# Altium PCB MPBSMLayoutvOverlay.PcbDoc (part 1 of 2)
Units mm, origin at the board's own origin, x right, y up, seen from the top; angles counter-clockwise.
Board outline 99.82 x 98.31 mm, 4 copper layers (Top Layer, Power, GroundPlane, Bottom Layer), stack 2.286 mm thick; 142 components, 77 nets, 390 pads, 126 vias.
Unrouted connection lines stored in the file: 1.
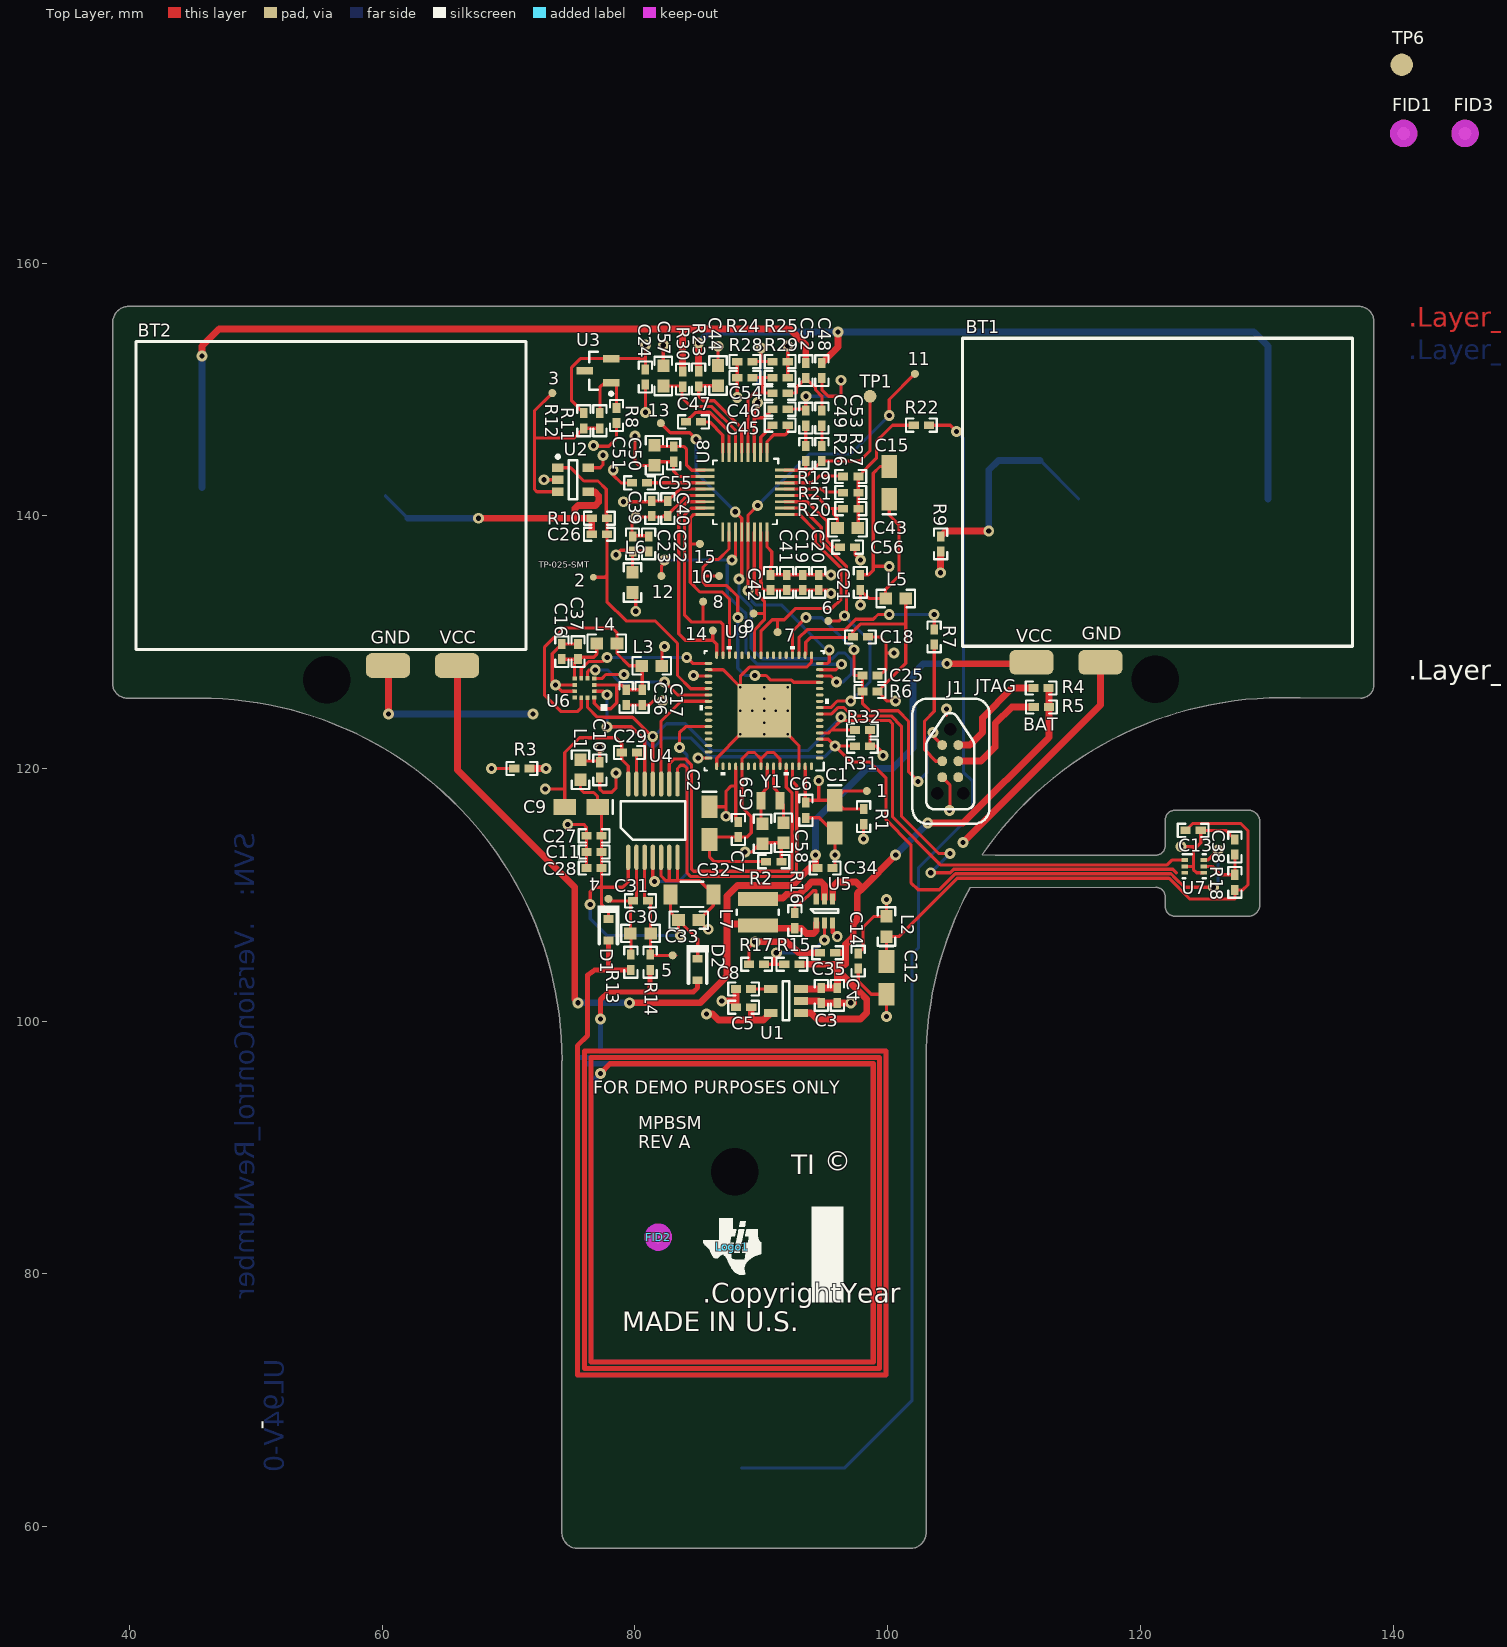
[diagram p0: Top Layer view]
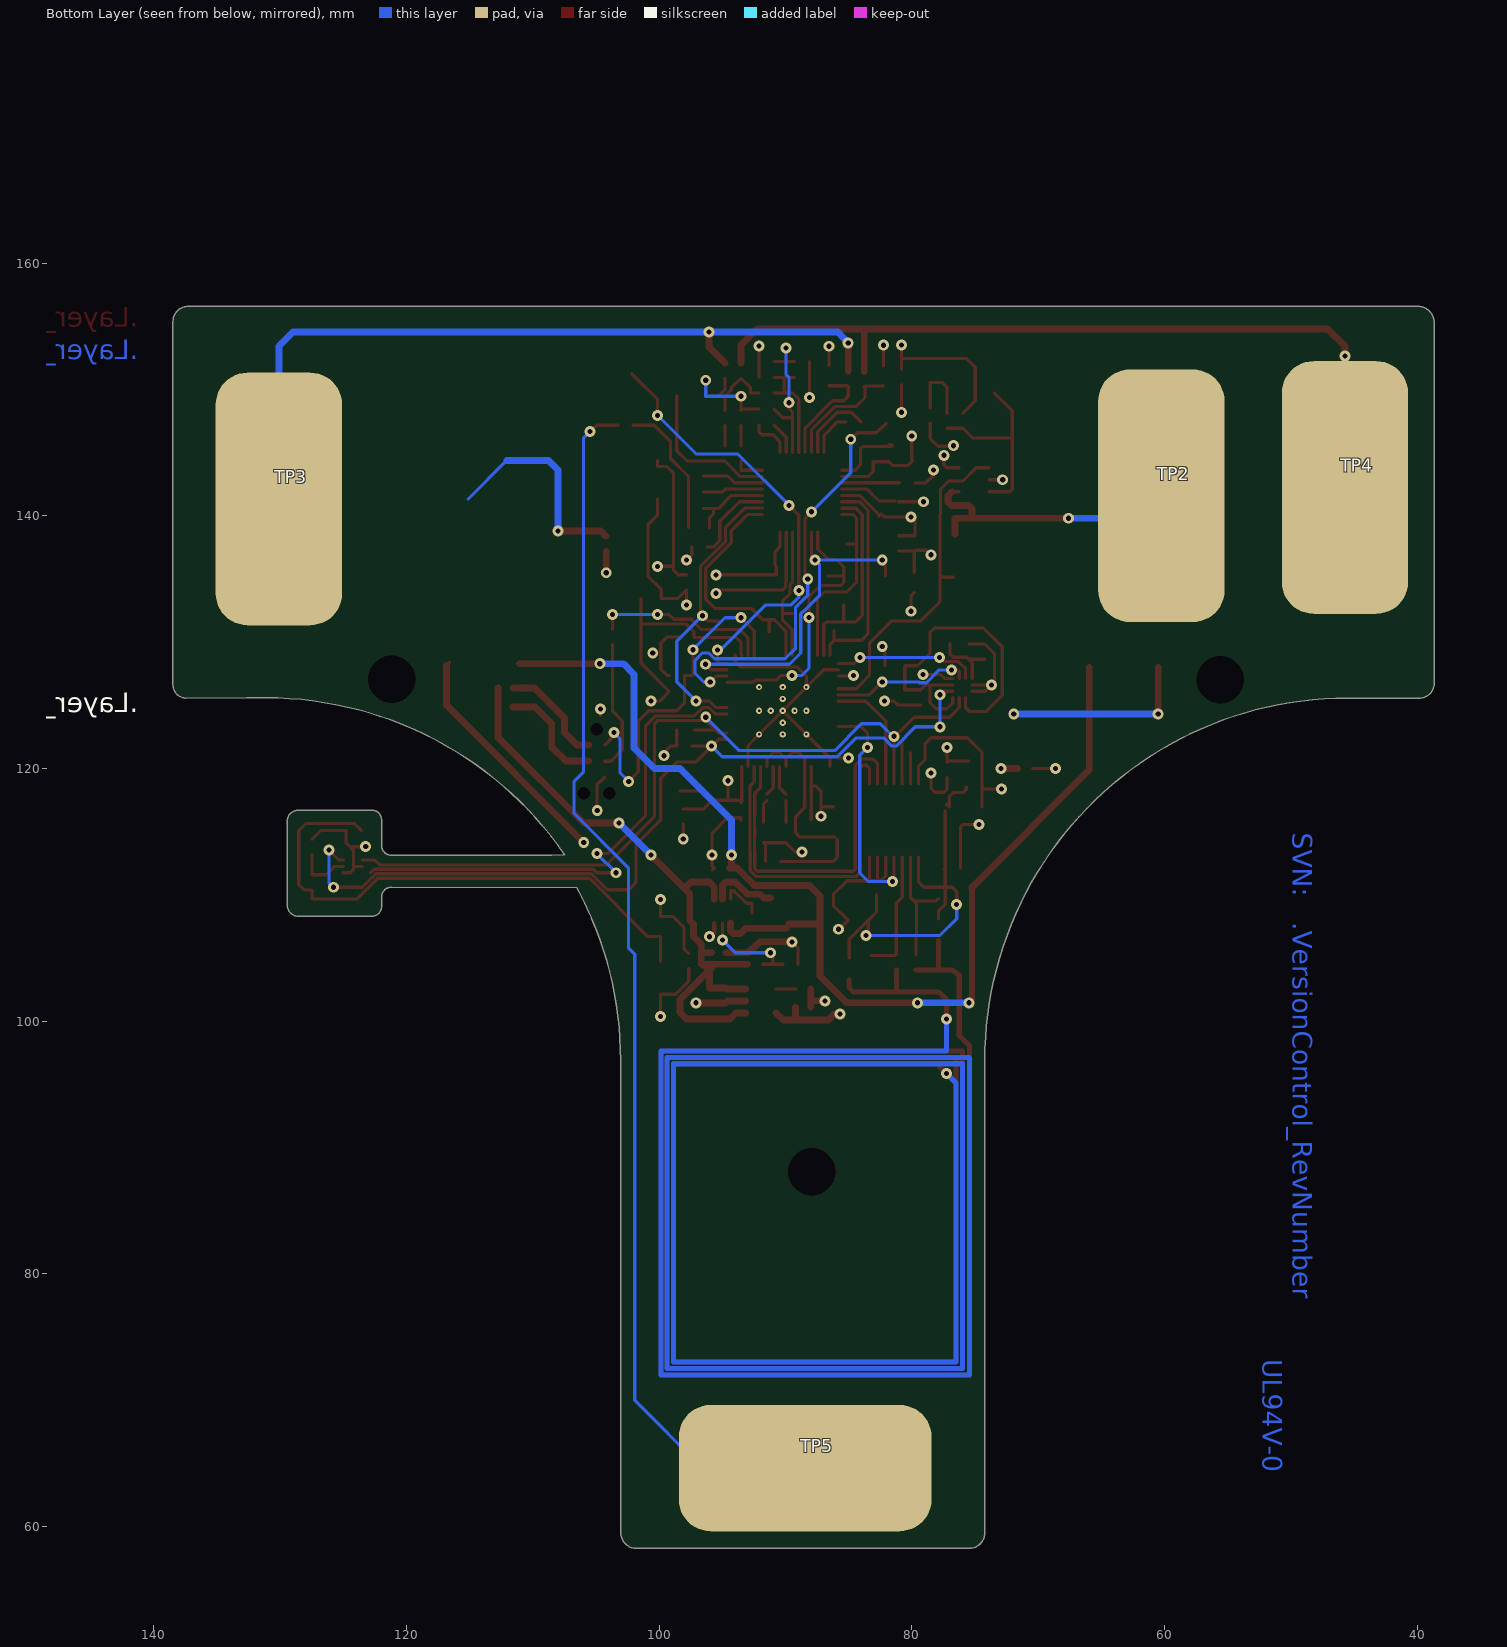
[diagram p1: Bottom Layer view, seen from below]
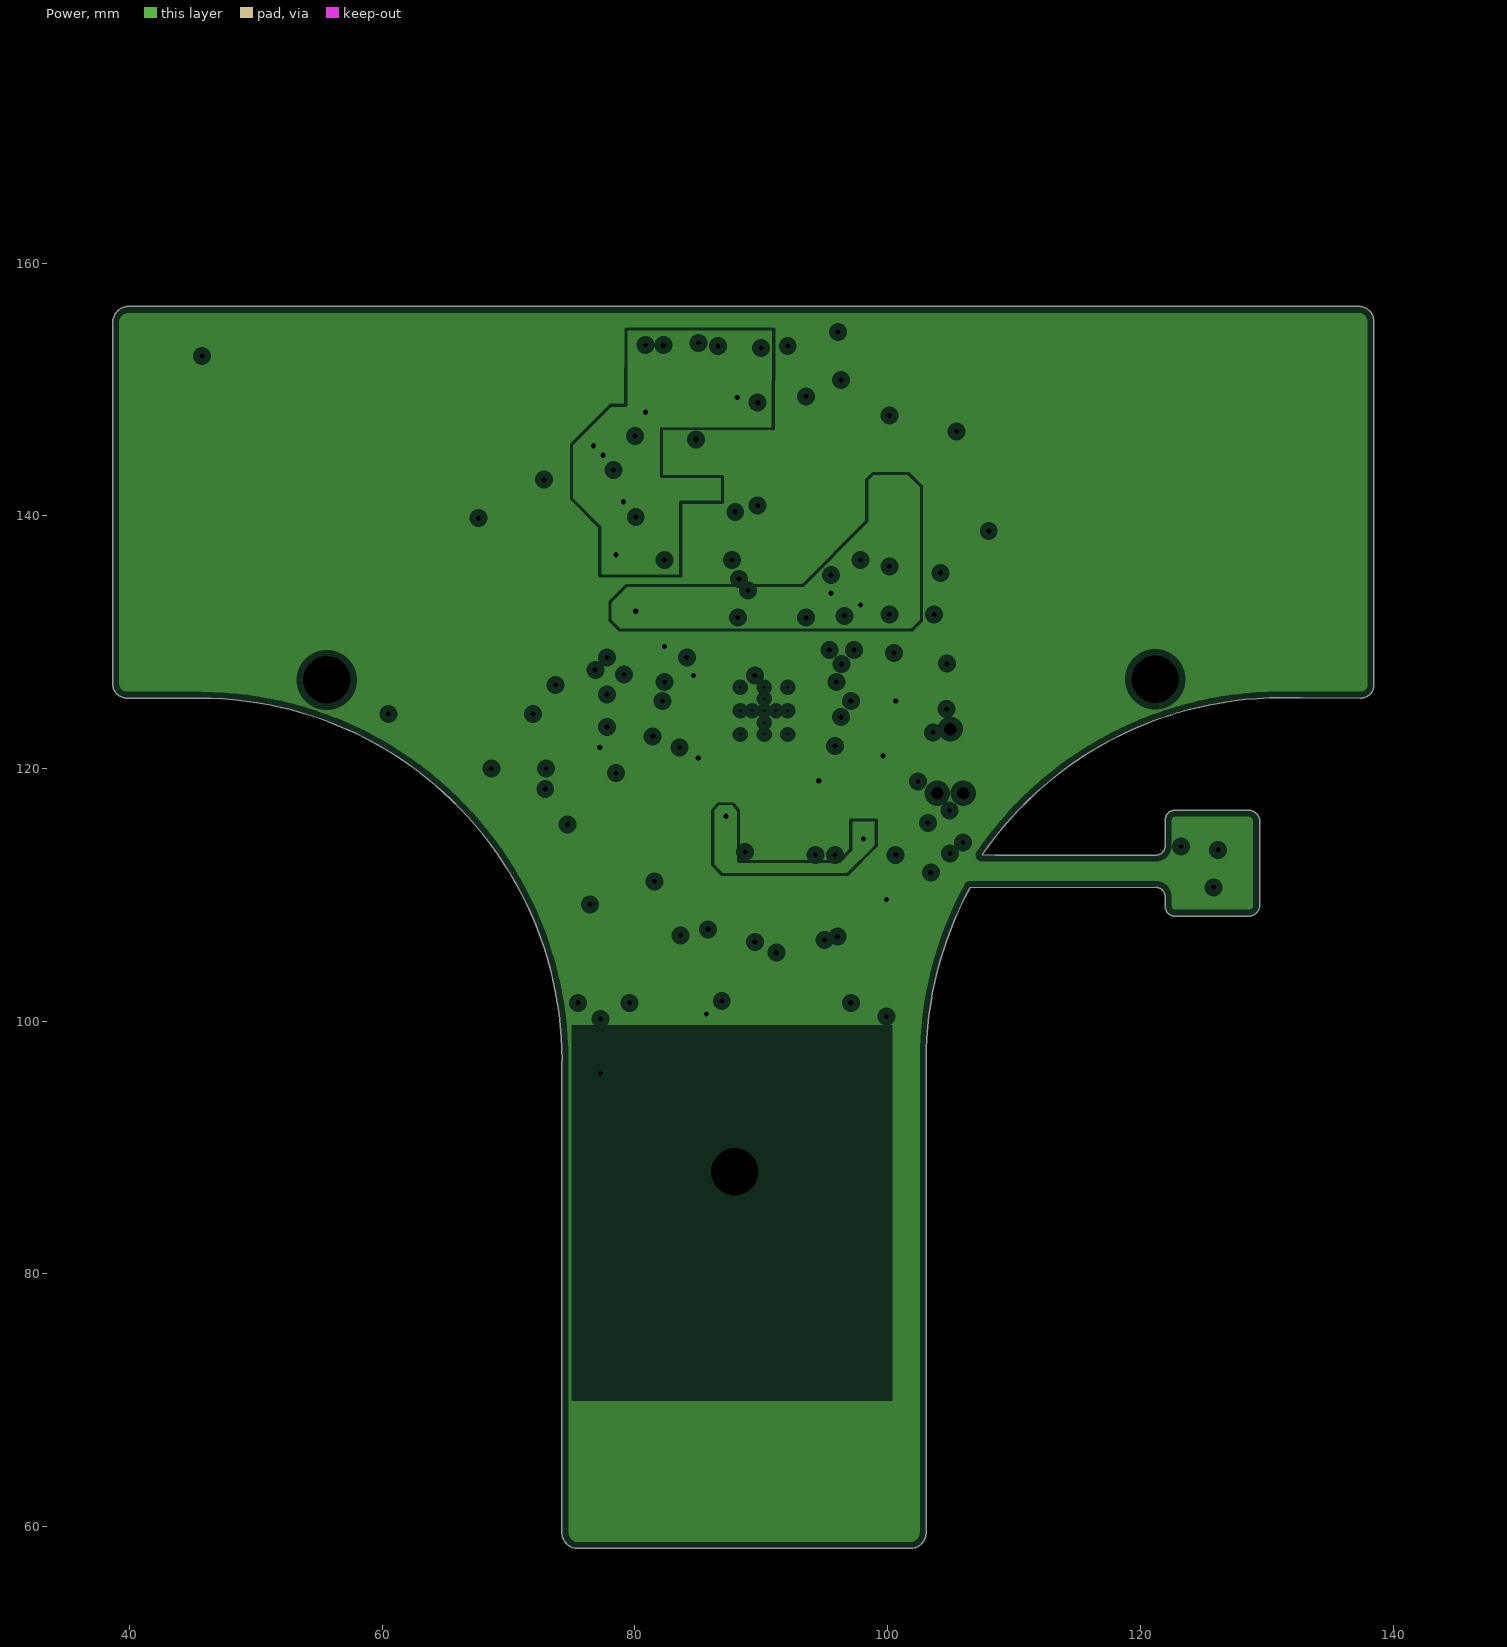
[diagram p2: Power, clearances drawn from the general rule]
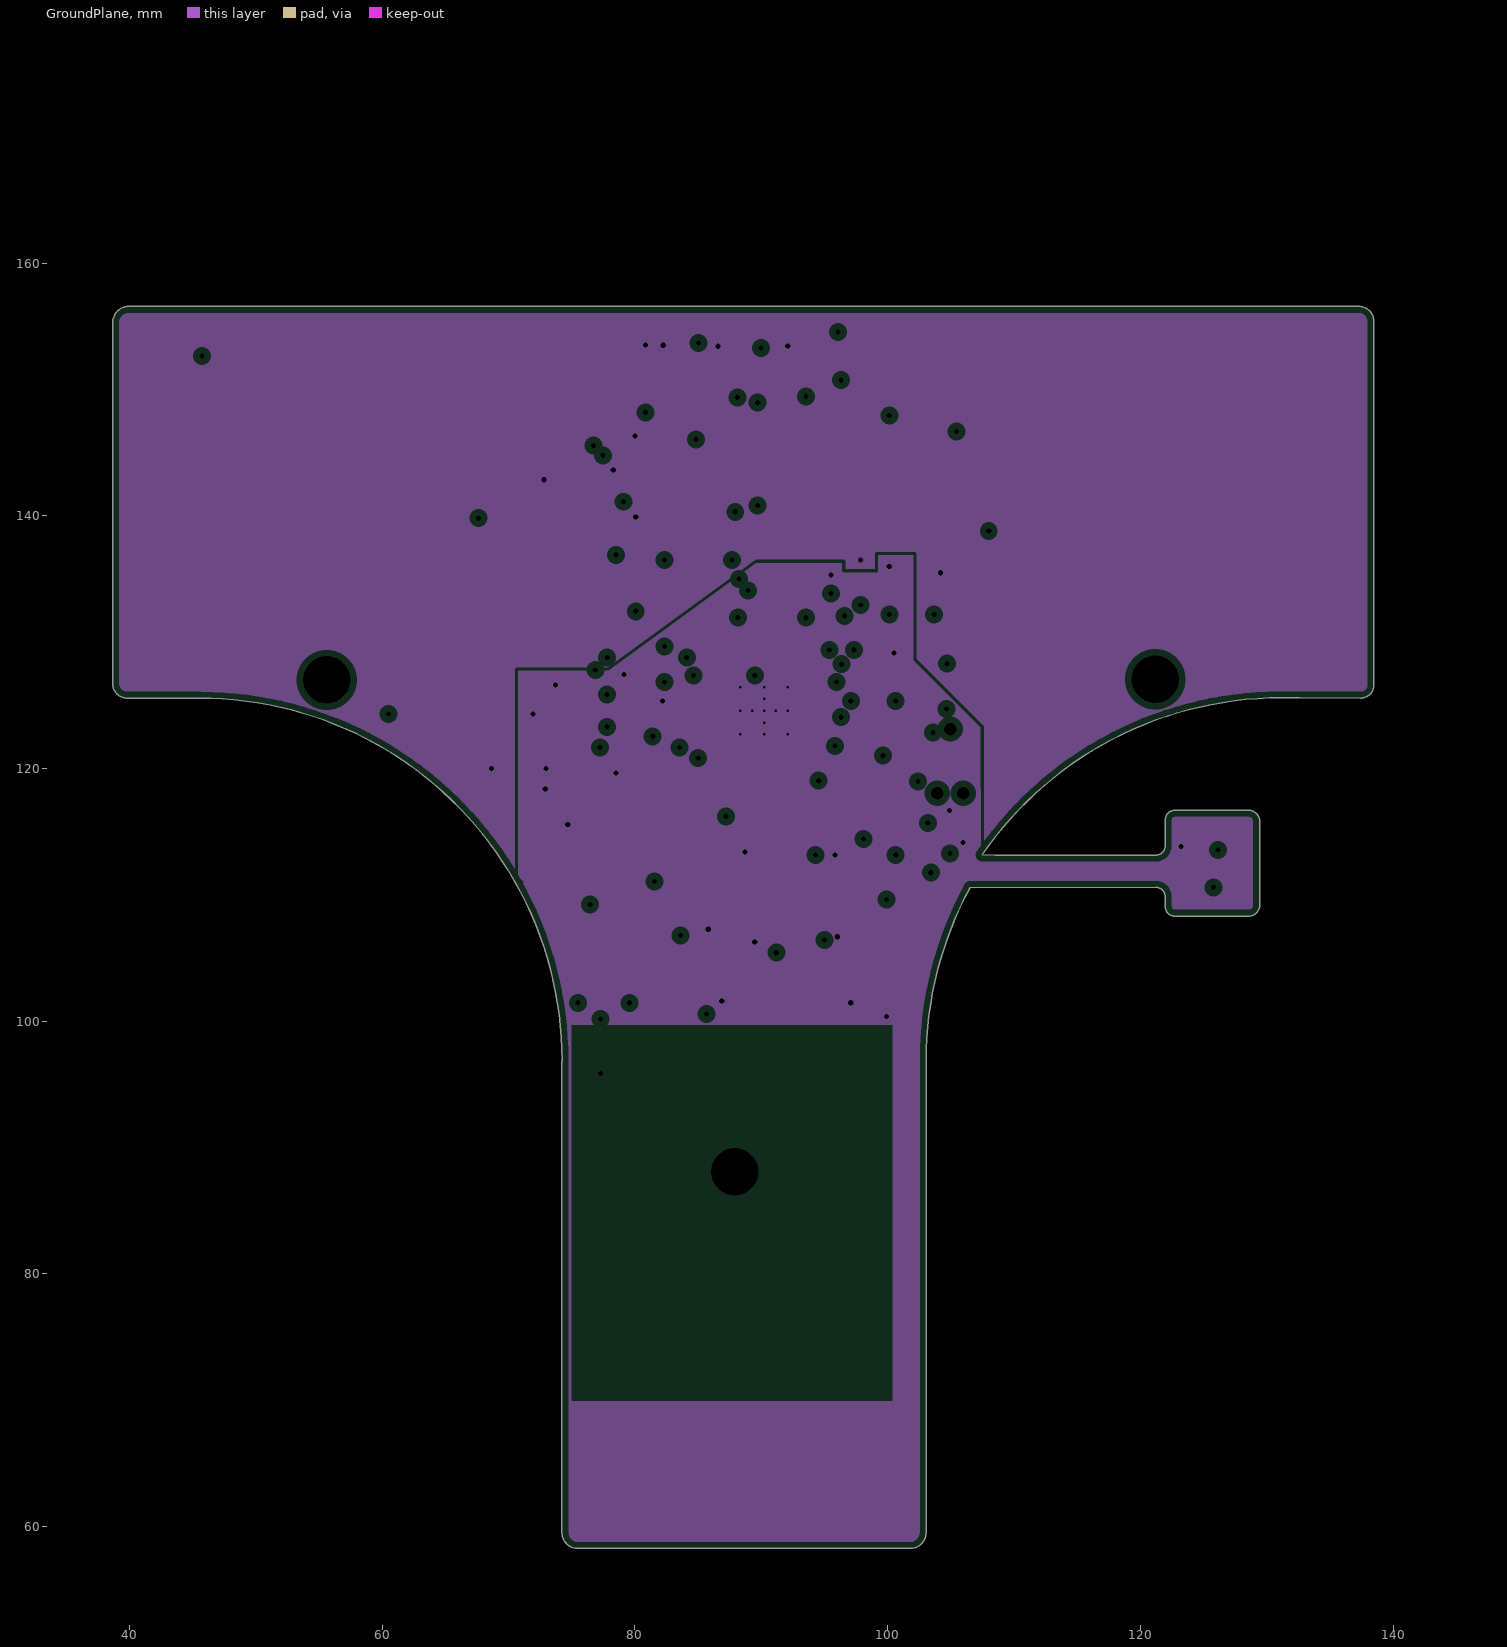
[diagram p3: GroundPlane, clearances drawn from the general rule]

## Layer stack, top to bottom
Top Solder: solder mask 0.0102, Solder Resist, Dk 3.5
Top Layer: signal copper 0.0356
Dielectric1: core 1.5037, FR-4, Dk 4.8
Power: plane copper 0.0356, net (Multiple Nets)
Dielectric2: prepreg 0.32, FR-4, Dk 4.8
GroundPlane: plane copper 0.0356, net (Multiple Nets)
Dielectric3: core 0.32, FR-4, Dk 4.8
Bottom Layer: signal copper 0.0356
Bottom Solder: solder mask 0.0102, Solder Resist, Dk 3.5

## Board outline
74.219,59.527 ccw(c75.489,59.527) 75.489,58.257 101.778,58.257 ccw(c101.778,59.527) 103.048,59.527 103.048,96.875 cw(c131.74,96.875) 106.525,110.565 121.209,110.592 cw(c121.209,109.83) 121.971,109.83 121.971,109.068 ccw(c122.733,109.068) 122.733,108.306 128.575,108.306 ccw(c128.575,109.173) 129.442,109.173 129.442,115.82 ccw(c128.575,115.82) 128.575,116.688 122.733,116.688 ccw(c122.733,115.926) 121.971,115.926 121.971,113.894 cw(c121.209,113.894) 121.209,113.132 108.509,113.132 107.469,113.147 cw(c131.115,96.896) 131.115,125.588 132.639,125.576 137.454,125.567 ccw(c137.454,126.594) 138.481,126.594 138.481,155.379 ccw(c137.294,155.379) 137.294,156.566 39.929,156.566 ccw(c39.929,155.296) 38.659,155.296 38.659,126.714 38.657,126.714 ccw(c39.804,126.714) 39.804,125.568 45.537,125.568 cw(c45.537,96.876) 74.229,96.876 74.219,96.875

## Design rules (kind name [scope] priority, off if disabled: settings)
AcuteAngle [All] p1: minimum=4.50000000000000E+0001 checktracksonly=FALSE
AssemblyTestPointUsage [All] p1: valid=2
Clearance Clearance_BoardEdge_MountingHoles [OnCopper and InComponentClass('Mounting Holes') vs IsKeepOut] p1: gap=1.016
Clearance Clearance_BoardEdge_Poly [OnCopper and InPoly vs IsKeepOut] p2: gap=0.635
Clearance Clearance_BoardEdge [OnCopper and Not InComponentClass('Logo') and not InComponentClass('FiducialMark') and not InRegion(1000,500,4000,800) and Not IsKeepout vs IsKeepOut] p3: gap=1.905
Clearance Clearance_Poly [InPolygon] p4: gap=0.635
Clearance [All] p5: gap=0.1
ComponentClearance ComponentClearance_Shunt [InComponentClass('Header') vs InComponentClass('Shunt')] p1: gap=0 collisioncheckmode=3 verticalgap=0 showdistances=FALSE
ComponentClearance ComponentClearance_MountingHoles_FiducialMarks [InComponentClass('Mounting Holes') vs InComponentClass('FiducialMark')] p2: gap=1.27 collisioncheckmode=3 verticalgap=0.254 showdistances=FALSE
ComponentClearance ComponentClearance_Logo [InComponentClass('Logo')] p3: gap=1.27 collisioncheckmode=3 verticalgap=0.254 showdistances=FALSE
ComponentClearance ComponentClearance_ScrewToNut [(HasFootprint('NY PMS 440 0025 PH')) vs (HasFootprint('Keystone_1902C'))] p4: gap=0.127 collisioncheckmode=3 verticalgap=0.254 showdistances=FALSE
ComponentClearance ComponentClearance_MountingHoles [InComponentClass('Mounting Holes')] p5: gap=6.35 collisioncheckmode=3 verticalgap=2540 showdistances=FALSE
ComponentClearance ComponentClearance_SmallPassives [HasFootprint('0201*') or HasFootprint('0402*') or HasFootprint('0508') or HasFootprint('0603*') or HasFootprint('0612') or HasFootprint('0805*') or HasFootprint('0815*') or HasFootprint('0830*') or HasFootprint('1206*') or HasFootprint('1210*') or HasFootprint('1808*') or HasFootprint('1812*') or HasFootprint('1825*') or HasFootprint('2010*') or HasFootprint('2220*') or HasFootprint('2225*') or HasFootprint('2512*') or HasFootprint('2728*') or HasFootprint('3518*') vs HasFootprint('0201*') or HasFootprint('0402*') or HasFootprint('0508') or HasFootprint('0603*') or HasFootprint('0612') or HasFootprint('0805*') or HasFootprint('0815*') or HasFootprint('0830*') or HasFootprint('1206*') or HasFootprint('1210*') or HasFootprint('1808*') or HasFootprint('1812*') or HasFootprint('1825*') or HasFootprint('2010*') or HasFootprint('2220*') or HasFootprint('2225*') or HasFootprint('2512*') or HasFootprint('2728*') or HasFootprint('3518*')] p6: gap=0.508 collisioncheckmode=3 verticalgap=0.254 showdistances=FALSE
ComponentClearance ComponentClearance_THtoSMT [IsThruComponent vs IsSMTComponent] p7: gap=2.54 collisioncheckmode=3 verticalgap=0.762 showdistances=FALSE
ComponentClearance ComponentClearance_THtoTH [IsThruComponent vs IsThruComponent] p8: gap=3 collisioncheckmode=3 verticalgap=0.762 showdistances=FALSE
ComponentClearance [All] p9: gap=1.016 collisioncheckmode=3 verticalgap=0.254 showdistances=FALSE
DiffPairsRouting [All] p1: maxlimit=2.54 minlimit=0.254 mostfreqgap=0.254 toplayer_minwidth=0.381 toplayer_maxwidth=0.381 toplayer_prefwidth=0.381 bottomlayer_minwidth=0.381 bottomlayer_maxwidth=0.381 bottomlayer_prefwidth=0.381 maxuncoupledlength=25.4
FabricationTestPointUsage TestPointUsage [All] p1: valid=2 allowmultiple=FALSE
FabricationTestpoint Testpoint [All] p1: side=3 testpointundercomponent=TRUE minsize=1.016 maxsize=2.54 preferedsize=1.524 minholesize=0 maxholesize=1.016 preferedholesize=0.813 testpointgrid=0.025 allowsidetop=TRUE allowsidebottom=TRUE usegrid=TRUE gridtolerance=0
FanoutControl Fanout_LCC [IsLCC] p1: bgadir=Out bgaviamode=Centered fanoutstyle=Auto fanoutdirection=Alternating viagrid=0.025 // Fanout_LCC (Default Rule)
FanoutControl Fanout_BGA [IsBGA] p2: bgadir=Out bgaviamode=Centered fanoutstyle=Auto fanoutdirection=Alternating viagrid=0.025 // Fanout_BGA (Default Rule)
FanoutControl Fanout_Default [All] p4: bgadir=Out bgaviamode=Centered fanoutstyle=Auto fanoutdirection=Alternating viagrid=0.025 // Fanout_Default (Default Rule)
FanoutControl Fanout_Small [(CompPinCount < 5)] p5: bgadir=Out bgaviamode=Centered fanoutstyle=Auto fanoutdirection=OutThenIn viagrid=0.025 // Fanout_Small (Default Rule)
Height [All] p1: minheight=0 maxheight=55.4 prefheight=12.7
HoleSize [All] p1: absolutevalues=TRUE maxlimit=6.375 minlimit=0.1 maxpercent=80.000 minpercent=20.000
MinimumAnnularRing MinimumAnnularRing_ThermalPadVias [IsVia and InAnyComponent] p1: minimumring=0.15
MinimumAnnularRing [All] p2: minimumring=0.229
MinimumSolderMaskSliver MinimumSolderMaskSliver_Logo [InComponentClass('Logo') vs InComponentClass('Logo')] p1: minsoldermaskwidth=0.018
MinimumSolderMaskSliver [All] p2: minsoldermaskwidth=0.08
PlaneClearance [All] p1: clearance=0.508
PlaneConnect [All] p1: planeconnectstyle=Relief reliefexpansion=0.254 reliefentries=4 reliefconductorwidth=0.254 reliefairgap=0.254
PolygonConnect [All] p1: connectstyle=Relief reliefconductorwidth=0.254 reliefentries=4 polygonreliefangle="90 Angle" airgapwidth=0.254
RoutingVias ThermalPadVias [IsVia and InAnyComponent] p1: holewidth=0.2 width=0.5 viastyle="Through Hole" minholewidth=0.2 minwidth=0.5 maxholewidth=0.33 maxwidth=0.6
RoutingVias [All] p2: holewidth=0.406 width=0.864 viastyle="Through Hole" minholewidth=0.2 minwidth=0.66 maxholewidth=1.016 maxwidth=1.651
SMDToCorner [All] p1: distance=30000
SilkToSilkClearance SilkToSilkClearance_Pb-FreeLogo [(HasFootprint('Pb-Free_Overlay_Medium') OR HasFootprint('Pb-Free_Overlay_Small')) vs (HasFootprint('Pb-Free_Overlay_Medium') OR HasFootprint('Pb-Free_Overlay_Small'))] p1: silktosilkclearance=0
SilkToSilkClearance [All] p2: silktosilkclearance=0
SilkToSolderMaskClearance SilkscreenOverComponentPads [IsPad] p1: minsilkscreentomaskgap=0.127 clearancetoexposedcopper=TRUE
SolderMaskExpansion [All] p1: expansion=0.05
Width [All] p1: maxlimit=2.54 minlimit=0.152 preferedwidth=0.254 checkconnectedcopper=TRUE
14 further rules are at their usual default settings.

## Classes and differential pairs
component class Transponder: 4 5 C27 C28 C29 C30 C31 C32 C33 D1 D2 R13 R14 U4
component class Temperature: C38 R18 U7
component class "Power Filtering": 1 C1 C2 C3 C4 C5 C6 C7 C8 C9 C10 C11 C12 C13 C14 C15 C16 C17 C18 C19 C20 C21 C22 C23 C24 L1 L2 L3 L4 L5 L6 R1 R2 R3 U1
component class MSP430FR5XXX: C58 C59 R31 R32 U9 Y1
component class "JTAG SPY-BY-WIRE": C25 J1 R4 R5 R6 R7
component class GSR: 2 3 C26 R8 R9 R10 R11 R12 U2 U3
component class ECG: 6 7 8 9 10 11 12 13 14 15 C39 C40 C41 C42 C43 C44 C45 C46 C47 C48 C49 C50 C51 C52 C53 C54 C55 C56 C57 R19 R20 R21 R22 R23 R24 R25 R26 R27 R28 R29 R30 TP1 U8
component class "Boost Converter": C34 C35 L7 R15 R16 R17 U5
component class BMA280: C36 C37 U6
component class Battery: BT1 BT2 U?
component class AssemblyNote: ZZ1 ZZ2 ZZ3 ZZ4
component class FiducialMark: FID1 FID2 FID3
component class Designator: FID1 FID2 FID3 Logo1 ZZ1 ZZ2 ZZ3 ZZ4
component class Logo: Logo1

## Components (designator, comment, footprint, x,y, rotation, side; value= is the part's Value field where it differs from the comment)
1 "TP-025-SMT" TP_25MIL-SMT#1 98.349,118.212 r90 top
2 "TP-025-SMT" TP_25MIL-SMT#2 76.708,135.128 r0 top
3 "TP-025-SMT" TP_25MIL-SMT#1 73.457,149.708 r0 top
4 "TP-025-SMT" TP_25MIL-SMT#1 77.897,109.676 r0 top
5 "TP-025-SMT" TP_25MIL-SMT#1 82.982,105.207 r270 top
6 "TP-025-SMT" TP_25MIL-SMT#1 95.301,131.674 r0 top
7 "TP-025-SMT" TP_25MIL-SMT#1 91.288,130.785 r0 top
8 "TP-025-SMT" TP_25MIL-SMT#1 85.395,133.198 r0 top
9 "TP-025-SMT" TP_25MIL-SMT#1 89.383,132.258 r0 top
10 "TP-025-SMT" TP_25MIL-SMT#1 86.665,135.23 r0 top
11 "TP-025-SMT" TP_25MIL-SMT#1 102.159,151.232 r0 top
12 "TP-025-SMT" TP_25MIL-SMT#1 82.093,135.23 r0 top
13 "TP-025-SMT" TP_25MIL-SMT#1 82.042,147.32 r0 top
14 "TP-025-SMT" TP_25MIL-SMT#1 86.157,130.912 r90 top
15 "TP-025-SMT" TP_25MIL-SMT#1 85.141,137.77 r0 top
BT1 "XXXXXX" Flat_Battery#1 114.046,128.524 r0 top
BT2 "XXXXXX" Flat_Battery#2 63.246,128.27 r180 top
C1 "293D106X9010A2TE3" 3216-18 95.809,116.18 r270 top
C2 "293D106X9010A2TE3" 3216-18 85.903,115.672 r270 top
C3 "C1005X5R1A104K" 0402 94.747,102.028 r270 top
C4 "C1005X5R0J105M" 0402 96.017,102.028 r270 top
C5 "C1005X5R1C225K050BC" 0402 88.6,101.092 r180 top
C6 "C1005X5R1A104K" 0402 93.523,116.688 r270 top
C7 "C1005X5R1A104K" 0402 88.189,115.164 r270 top
C8 "C1005X7R1E103K" 0402 88.595,102.54 r180 top
C9 "293D105X9016A2TE3" 3216-18 75.743,116.942 r180 top
C10 "C1005X5R1A104K" 0402 77.216,119.888 r270 top
C11 "C1005X5R1A104K" 0402 76.759,113.386 r180 top
C12 "293D106X9010A2TE3" 3216-18 99.906,103.422 r270 top
C13 "C1005X5R1A104K" 0402 124.183,115.089 r0 top
C14 "C1005X5R1A104K" 0402 97.665,104.75 r270 top
C15 "293D105X9016A2TE3" 3216-18 100.127,142.596 r90 top
C16 "CL05A106MQ5NUNC" 0402 74.219,129.247 r90 top
C17 "CL05A106MQ5NUNC" 0402 80.569,125.624 r270 top
C18 "C1005X5R1A104K" 0402 97.841,130.404 r0 top
C19 "C1005X5R1A104K" 0402 93.269,134.722 r90 top
C20 "C1005X5R1C225K050BC" 0402 94.539,134.722 r90 top
C21 "CL05A106MQ5NUNC" 0402 97.841,134.722 r90 top
C22 "CL05A106MQ5NUNC" 0402 81.077,137.77 r90 top
C23 "C1005X5R1A104K" 0402 79.807,137.77 r90 top
C24 "C1005X5R1A104K" 0402 80.823,150.978 r90 top
C25 "C1005X8R1H222K" 0402 98.603,127.356 r0 top
C26 "C1005X7R1E103K" 0402 77.175,138.532 r180 top
C27 "C1005X5R0J105M" 0402 76.759,114.656 r180 top
C28 "C1005X5R1A104K" 0402 76.759,112.116 r180 top
C29 "GRM155R60J474KE19D" 0402 79.553,121.26 r0 top
C30 "C1608C0G1H330J" 0603 80.437,106.941 r0 top
C31 "GRM1555C1H390JA01D" 0402 80.437,109.515 r0 top
C32 "C3216X5R1A107M160AC" 1206_190 84.501,110.023 r0 top
C33 "Used in BOM report" 0603 84.247,107.991 r0 top
C34 "CL05A106MQ5NUNC" 0402 95.047,112.116 r0 top
C35 "CL05A106MQ5NUNC" 0402 95.25,105.41 r180 top
C36 "C1005X5R1A104K" 0402 79.299,125.624 r270 top
C37 "C1005X5R1A104K" 0402 75.489,129.247 r90 top
C38 "C1005X7R1E103K" 0402 127.485,113.773 r90 top
C39 "C1005X5R1C105K050BC" 0402 81.331,140.564 r270 top
C40 "C1005X5R1A104K" 0402 82.601,140.564 r270 top
C41 "C1005X5R1C105K050BC" 0402 91.999,134.722 r90 top
C42 "C1005X5R1A104K" 0402 90.729,134.722 r90 top
C43 "C0603C152K5RACTU" 0603 96.825,139.04 r180 top
C44 "GRM1885C1H302JA01D" 0603 86.563,151.091 r90 top
C45 "GRM155R61A472KA01D" 0402 91.491,147.168 r0 top
C46 "C1005X8R1H222K" 0402 91.491,148.438 r0 top
C47 "GRM155R61A472KA01D" 0402 84.633,147.422 r180 top
C48 "C1005X5R1A104K" 0402 94.793,151.486 r270 top
C49 "C1005X8R1H222K" 0402 93.523,147.722 r90 top
C50 "C1005X5R1A104K" 0402 83.058,144.872 r270 top
C51 "C1608X5R0J106M" 0603 81.534,144.78 r270 top
C52 "C1005X5R1A104K" 0402 93.523,151.486 r270 top
C53 "C1005X8R1H222K" 0402 94.793,147.722 r90 top
C54 "C1005X8R1H222K" 0402 91.491,149.708 r0 top
C55 "C1005X5R1C105K050BC" 0402 80.361,142.596 r180 top
C56 "C1005X5R1C105K050BC" 0402 96.825,137.516 r0 top
C57 "GRM1885C1H302JA01D" 0603 82.241,151.063 r90 top
C58 "06035A100JAT2A" 0603 91.745,114.91 r270 top
C59 "06035A100JAT2A" 0603 90.094,114.833 r270 top
D1 "CDBU0130L" SOD-523F 77.897,107.229 r270 top
D2 "CDBU0130L" SOD-523F 84.963,104.089 r270 top
FID1 "Fiducial" Fiducial10-20 140.843,170.256 r0 top
FID2 "Fiducial" Fiducial10-20 81.839,82.906 r0 top
FID3 "Fiducial" Fiducial10-20 145.694,170.256 r0 top
J1 "TC2030-MCP-NL" TC2030-MCP-NL 104.953,120.574 r180 top
L1 "BLM18HG601SN1D" 0603 75.692,119.888 r270 top
L2 "BLM18HG601SN1D" 0603 99.906,107.486 r270 top
L3 "BLM18HG601SN1D" 0603 81.331,128.118 r180 top
L4 "BLM18HG601SN1D" 0603 77.775,129.896 r0 top
L5 "BLM18HG601SN1D" 0603 100.635,133.452 r180 top
L6 "BLM18HG601SN1D" 0603 79.807,134.722 r90 top
L7 "EPL3015-472MLB" EPL3015 89.738,108.61 r90 top
Logo1 "Texas Instruments" TI_Symbol_Overlay_Small 87.681,82.144 r0 top
R1 "ERJ-2GE0R00X" 0402 98.095,116.18 r270 top
R2 "ERJ-2GE0R00X" 0402 90.983,112.624 r180 top
R3 "ERJ-2GE0R00X" 0402 71.046,119.99 r180 top
R4 "ERJ-2GE0R00X" 0402 112.141,126.365 r0 top
R5 "ERJ-2GE0R00X" 0402 112.16,124.861 r0 top
R6 "CRCW040247K0JNED" 0402 98.603,126.086 r0 top
R7 "ERJ-2GE0R00X" 0402 103.683,130.404 r90 top
R8 "CRCW040221K5FKED" 0402 78.537,147.93 r270 top
R9 "CRCW040210K0FKED" 0402 104.191,137.77 r90 top
R10 "ERJ-2RKF1004X" 0402 77.175,139.802 r0 top
R11 "CRCW040211K8FKED" 0402 77.221,147.517 r90 top
R12 "CRCW04028K06FKED" 0402 75.951,147.517 r270 top
R13 "ERJ-2GE0R00X" 0402 79.675,104.655 r270 top
R14 "ERJ-2GE0R00X" 0402 81.199,104.655 r270 top
R15 "ERJ-2RKF1004X" 0402 92.415,104.496 r0 top
R16 "ERJ-2GE0R00X" 0402 92.659,107.95 r90 top
R17 "ERJ-2RKF2003X" 0402 89.621,104.496 r0 top
R18 "CRCW04024K99FKED" 0402 127.485,110.979 r270 top
R19 "ERJ-2GE0R00X" 0402 97.079,143.104 r0 top
R20 "ERJ-2RKF1004X" 0402 97.079,140.564 r0 top
R21 "ERJ-2RKF1003X" 0402 97.079,141.834 r0 top
R22 "ERJ-2RKF1003X" 0402 102.667,147.168 r0 top
R23 "CRCW040251K1FKED" 0402 85.039,150.837 r270 top
R24 "CRCW040210M0FKED" 0402 88.697,152.202 r180 top
R25 "CRCW040210M0FKED" 0402 91.491,152.202 r180 top
R26 "CRCW040240K2FKED" 0402 93.523,144.928 r270 top
R27 "CRCW040240K2FKED" 0402 94.793,144.928 r270 top
R28 "CRCW040210M0FKED" 0402 88.697,150.932 r180 top
R29 "CRCW040210M0FKED" 0402 91.491,150.932 r180 top
R30 "CRCW040251K1FKED" 0402 83.765,150.809 r270 top
R31 "CRCW04023K30JNED" 0402 98.003,121.768 r180 top
R32 "CRCW04023K30JNED" 0402 98.003,123.038 r180 top
TP1 "TESTPOINT" TP_SM_1MM#1 98.603,149.454 r0 top locked
TP2 "TESTPOINT" TP_SM_1MM#2 60.249,141.58 r90 bottom
TP3 "TESTPOINT" TP_SM_1MM#2 130.099,141.326 r90 bottom
TP4 "TESTPOINT" TP_SM_1MM#2 45.72,142.24 r90 bottom
TP5 "TESTPOINT" TP_SM_1MM#3 88.443,64.618 r90 bottom
TP6 "Pogo Pad" PogoPad 140.691,175.692 r0 top
U1 "TPS73030DBVR" DBV0005A_N 91.948,101.6 r180 top
U2 "LMP2231AMFE" MF05A_L 75.097,142.85 r0 top
U3 "LM4041AIM3-1.2" MF03A_N 77.064,151.46 r180 top
U4 "RF430CL331HCPW" PW0014A_M 81.414,115.864 r90 top
U5 "TPS61220DCK" DCK0006A_N 94.996,108.712 r90 top
U6 "BMA280" LGA-12P 75.997,126.361 r90 top
U7 "TMP112AIDRL" DRL0006A 124.257,112.243 r0 top
U8 "ADS1292RIPBS" PBS0032A_N 88.697,141.853 r270 top
U9 "MSP430FR5889IRGCR" RGC0064B 90.221,124.562 r180 top
Y1 "FC-12M 32.7680KA-A3" Epson_FC-12M 90.729,117.45 r0 top
ZZ1 "This Assembly Note is for PCB labels only" AssemblyNoteLabel 35.992,195.631 r0 top
ZZ2 "These assemblies are ESD sensitive, ESD precautions shall be observed." AssemblyNote 35.992,192.865 r0 top
ZZ3 "These assemblies must be clean and free from flux and all contaminants. Use of no clean flux is not acceptable." AssemblyNote 35.992,190.616 r0 top
ZZ4 "These assemblies must comply with workmanship standards IPC-A-610 Class 2, unless otherwise specified." AssemblyNote 35.992,188.366 r0 top

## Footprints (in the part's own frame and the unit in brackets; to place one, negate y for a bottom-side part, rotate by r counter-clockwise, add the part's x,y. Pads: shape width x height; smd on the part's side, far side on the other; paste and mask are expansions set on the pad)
0402 [mm] "0402 from SM-752 data"
  rect 0.8x0.6 smd: 1(-0.6,0) 2(0.6,0)
  silkscreen extent -1.22,-0.52 1.22,0.52, body extent -0.55,-0.3 0.55,0.3, height 0.6
0603 [mm] "0603 from SM-752 data"
  rect 1x0.95 smd: 1(-0.8,0) 2(0.8,0)
  silkscreen extent -1.52,-0.69 1.52,0.69, body extent -0.87,-0.47 0.87,0.47, height 0.85
1206_190 [mm] "1206_190"
  rect 1.1x1.6 smd: 1(-1.7,0) 2(1.7,0)
  silkscreen extent -0.9,-1 0.9,1, body extent -1.75,-0.95 1.75,0.95, height 1.9
3216-18 [mm] "Medium density IPC, based on Kemet T495 dimensions"
  rect 1.8x1.25 smd: 1(-1.3,0) 2(1.3,0)
  silkscreen extent -2.49,-0.54 -2.49,0.54, body extent -1.7,-0.9 1.7,0.9, height 1.8
AssemblyNote [mm] "Assembly Note"
AssemblyNoteLabel [mm] "Assembly Note for PCB Labels"
DBV0005A_N [mm] "SOT23, 5-Leads, Body 2.9x1.6mm, Pitch 0.95mm, Lead Span 2.8mm, IPC Medium Density"
  rect 1.1x0.65 smd: 1(-1.2,0.95) 2(-1.2,0) 3(-1.2,-0.95) 4(1.2,-0.95) 5(1.2,0.95)
  silkscreen extent -0.25,-1.55 0.25,1.55, body extent -1.42,-1.46 1.42,1.46, height 1.08
DCK0006A_N [mm] "SOT23, 6-Leads, Body 2x1.3mm, Pitch 0.65mm, Lead Span 2.1mm, IPC Medium Density"
  rect 0.85x0.4 smd: 1(-0.95,0.65) 2(-0.95,0) 3(-0.95,-0.65) 4(0.95,-0.65) 5(0.95,0) 6(0.95,0.65)
  silkscreen extent -0.15,-1.1 0.15,1.1, body extent -1.14,-1 1.14,1, height 0.94
DRL0006A [mm] "SOTFL, 6-Flat Leads, Body 1.2x1.6x0.6mm, Pitch 0.5mm, TI recommended"
  rect 0.5x0.3 smd: 1(-0.75,0.5) 2(-0.75,0) 3(-0.75,-0.5) 4(0.75,-0.5) 5(0.75,0) 6(0.75,0.5)
  silkscreen extent -0.9,-0.95 0.9,0.95, body extent -0.85,-0.85 0.85,0.85, height 0.62
EPL3015 [mm] "COILCRAFT"
  rect 1.12x3.2 smd: 1(-1.04,0) 2(1.04,0)
  silkscreen extent -0.22,-1.65 0.23,1.68, body extent -1.6,-1.6 1.6,1.6, height 1.55
Epson_FC-12M [mm] "Epson"
  rect 0.7x1.4 smd: 1(-0.75,0) 2(0.75,0)
  body extent -1.05,-0.63 1.05,0.63, height 0.6
Fiducial10-20 [mm]
  round 1 smd mask+0.5: 1(0,0)
  Top Layer keep-out circle w1.178: c0,0 r0.5
Flat_Battery#1 [mm]
  rrect50% 3.5x1.95 smd: 1(-2.667,-0.127) 2(2.794,-0.127)
  silkscreen extent -8.13,1.14 22.73,25.53, body extent -8.13,1.14 22.73,25.53, height 1
Flat_Battery#2 [mm]
  rrect50% 3.5x1.95 smd: 1(-2.667,0.127) 2(2.794,0.127)
  silkscreen extent -8.13,-25.53 22.73,-1.14, body extent -8.13,-25.53 22.73,-1.14, height 1
LGA-12P [mm]
  rect 0.3x0.35 smd mask+0.05: 1(-0.75,-0.775) 2(-0.25,-0.775) 3(0.25,-0.775) 4(0.75,-0.775) 7(0.75,0.775) 8(0.25,0.775) 9(-0.25,0.775) 10(-0.75,0.775)
  rect 0.35x0.3 smd mask+0.05: 5(0.775,-0.25) 6(0.775,0.25) 11(-0.775,0.25) 12(-0.775,-0.25)
  silkscreen extent -1.8,-1.8 -1.29,-1.3
MF03A_N [mm] "SOT23, 3-Leads, Body 2.9x1.3mm, Pitch 0.95mm, Lead Span 2.4mm, IPC Medium Density"
  rect 1.3x0.6 smd: 1(-1.05,0.95) 2(-1.05,-0.95) 3(1.05,0)
  silkscreen extent -1.18,-1.5 0.7,1.92, body extent -0.7,-1.5 0.7,1.5, height 1.12
MF05A_L [mm] "SOT23, 5-Leads, Body 2.9x1.6mm, Pitch 0.95mm, Lead Span 2.8mm, IPC High Density"
  rect 0.9x0.65 smd: 1(-1.2,0.95) 2(-1.2,0) 3(-1.2,-0.95) 4(1.2,-0.95) 5(1.2,0.95)
  silkscreen extent -1.32,-1.55 0.35,1.95, body extent -0.9,-1.55 0.9,1.55, height 1.19
PBS0032A_N [mil]
  rect 60x9 smd: 1(-124,68.9) 2(-124,49.21) 3(-124,29.53) 4(-124,9.84) 5(-124,-9.84) 6(-124,-29.53) 7(-124,-49.21) 8(-124,-68.9) 17(124,-68.9) 18(124,-49.21) 19(124,-29.53) 20(124,-9.84) 21(124,9.84) 22(124,29.53) 23(124,49.21) 24(124,68.9)
  rect 9x60 smd: 9(-68.9,-124) 10(-49.21,-124) 11(-29.53,-124) 12(-9.84,-124) 13(9.84,-124) 14(29.53,-124) 15(49.21,-124) 16(68.9,-124) 25(68.9,124) 26(49.21,124) 27(29.53,124) 28(9.84,124) 29(-9.84,124) 30(-29.53,124) 31(-49.21,124) 32(-68.9,124)
  silkscreen extent -104,-100 100,104, body extent -140,-140 140,140, height 48
PogoPad [mil] "No Solder Paste"
  round 70 smd paste-35: 1(0,0)
PW0014A_M [mm] "TSOP, 14-Leads, Body 5x4.4mm, Pitch 0.65mm, IPC Low Density"
  oval 2x0.35 smd: 1(-2.9,1.95) 2(-2.9,1.3) 3(-2.9,0.65) 4(-2.9,0) 5(-2.9,-0.65) 6(-2.9,-1.3) 7(-2.9,-1.95) 8(2.9,-1.95) 9(2.9,-1.3) 10(2.9,-0.65) 11(2.9,0) 12(2.9,0.65) 13(2.9,1.3) 14(2.9,1.95)
  silkscreen extent -1.5,-2.55 1.53,2.55, body extent -3.21,-2.5 3.21,2.5, height 0.98
RGC0064B [mm]
  oval 0.6x0.24 smd mask+0.07: 1(-4.4,3.75) 2(-4.4,3.25) 3(-4.4,2.75) 4(-4.4,2.25) 5(-4.4,1.75) 6(-4.4,1.25) 7(-4.4,0.75) 8(-4.4,0.25) 9(-4.4,-0.25) 10(-4.4,-0.75) 11(-4.4,-1.25) 12(-4.4,-1.75) 13(-4.4,-2.25) 14(-4.4,-2.75) 15(-4.4,-3.25) 16(-4.4,-3.75) 33(4.4,-3.75) 34(4.4,-3.25) 35(4.4,-2.75) 36(4.4,-2.25) 37(4.4,-1.75) 38(4.4,-1.25) 39(4.4,-0.75) 40(4.4,-0.25) 41(4.4,0.25) 42(4.4,0.75) 43(4.4,1.25) 44(4.4,1.75) 45(4.4,2.25) 46(4.4,2.75) 47(4.4,3.25) 48(4.4,3.75)
  oval 0.24x0.6 smd mask+0.07: 17(-3.751,-4.4) 18(-3.251,-4.4) 19(-2.751,-4.4) 20(-2.251,-4.4) 21(-1.75,-4.4) 22(-1.25,-4.4) 23(-0.75,-4.4) 24(-0.25,-4.4) 25(0.25,-4.4) 26(0.75,-4.4) 27(1.25,-4.4) 28(1.75,-4.4) 29(2.251,-4.4) 30(2.751,-4.4) 31(3.251,-4.4) 32(3.751,-4.4) 49(3.751,4.4) 50(3.251,4.4) 51(2.751,4.4) 52(2.251,4.4) 53(1.75,4.4) 54(1.25,4.4) 55(0.75,4.4) 56(0.25,4.4) 57(-0.25,4.4) 58(-0.75,4.4) 59(-1.25,4.4) 60(-1.75,4.4) 61(-2.251,4.4) 62(-2.751,4.4) 63(-3.251,4.4) 64(-3.751,4.4)
  rect 4.25x4.25 smd paste-2.112: 65(0,0)
  silkscreen extent -5.1,-5.1 5.1,5.1, body extent -4.57,-4.57 4.57,4.57, height 1.01
SOD-523F [mm] "COMCHIP"
  rect 0.6x0.8 smd paste-0.05: 1(-0.85,0) 2(0.85,0)
  silkscreen extent -1.92,-0.87 1.1,0.88, body extent -0.9,-0.5 0.9,0.5, height 0.85
TC2030-MCP-NL [mil] "TAG-CONNECT"
  round 31 smd paste-16: 1(-25,-50) 2(25,-50) 3(-25,0) 4(25,0) 5(-25,50) 6(25,50)
  round 25 hole 39 unplated: MH1(0,-100) MH2(-40,100) MH3(40,100)
  silkscreen extent -122,-195 118,195
TI_Symbol_Overlay_Small [mm]
  silkscreen extent -2.3,-2.23 2.3,2.24
TP_25MIL-SMT#1 [mm]
  round 0.635 smd mask-0.064: 1(0,0)
TP_25MIL-SMT#2 [mm]
  round 0.535 smd mask-0.064: 1(0,0)
TP_SM_1MM#1 [mm] "1mm Test Point, SMT"
  round 1 smd paste-0.5: 1(0,0)
TP_SM_1MM#2 [mm] "1mm Test Point, SMT"
  rrect50% 20x10 smd paste-0.5: 1(0,0)
TP_SM_1MM#3 [mm] "1mm Test Point, SMT"
  rrect50% 10x20 smd paste-0.5: 1(0,0)

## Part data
1 2 3 4 5 6 7 8 9 10 11 12 13 14 15: "Test Point, O.025\""
BT1 BT2: library part Battery, "Battery, Lithium Polymer, 3V, 25mAh"
C1 C2 C12: "CAP, TA, 10 µF, 10 V, +/- 10%, 3.4 ohm, SMD"
C3 C6 C7 C10 C11 C13 C14 C18 C19 C23 C24 C28 C36 C37 C40 C42 C48 C50 C52: "CAP, CERM, 0.1 µF, 10 V, +/- 10%, X5R, 0402"
C4 C27: "CAP, CERM, 1 µF, 6.3 V, +/- 20%, X5R, 0402"
C5 C20: "CAP, CERM, 2.2 µF, 16 V, +/- 10%, X5R, 0402"
C8 C26 C38: "CAP, CERM, 0.01 µF, 25 V, +/- 10%, X7R, 0402"
C9 C15: "CAP, TA, 1 µF, 16 V, +/- 10%, 9.3 ohm, SMD"
C16 C17 C21 C22 C34 C35: "CAP, CERM, 10 µF, 6.3 V, +/- 20%, X5R, 0402"
C25 C46 C49 C53 C54: "CAP, CERM, 2200 pF, 50 V, +/- 10%, X8R, 0402"
C29: "CAP, CERM, 0.47 µF, 6.3 V, +/- 10%, X5R, 0402"
C30: "CAP, CERM, 33 pF, 50 V, +/- 5%, C0G/NP0, 0603"
C31: "CAP, CERM, 39pF, 50V, +/-5%, C0G/NP0, 0402"
C32: "CAP, CERM, 100 µF, 10 V, +/- 20%, X5R, 1206_190"
C33: library part Capacitor, "CAP, CERM, xxxF, xxV, [TempCo], xx%, [PackageReference]"
C39 C41 C55 C56: "CAP, CERM, 1 µF, 16 V, +/- 10%, X5R, 0402"
C43: "CAP, CERM, 1500 pF, 50 V, +/- 10%, X7R, 0603"
C44 C57: "CAP, CERM, 3000 pF, 50 V, +/- 5%, C0G/NP0, 0603"
C45 C47: "CAP, CERM, 4700 pF, 10 V, +/- 10%, X5R, 0402"
C51: "CAP, CERM, 10 µF, 6.3 V, +/- 20%, X5R, 0603"
C58 C59: "CAP, CERM, 10 pF, 50 V, +/- 5%, C0G/NP0, 0603"
D1 D2: "Diode, Schottky, 35V, 0.1A, SOD-523F"
FID1 FID2 FID3: "Fiducial mark.  There is nothing to buy or mount."
J1: "Footprint for TC2030-MCP-NL"
L1 L2 L3 L4 L5 L6: "Ferrite Bead, 600 ohm @ 100MHz, 0.2A, 0603"
L7: "Inductor, Shielded, Ferrite, 4.7uH, 1.2A, 0.14 ohm, SMD"
Logo1: library part TI_Logo, "Texas Instrument Corporate Signature"
R1 R2 R3 R4 R5 R7 R13 R14 R16 R19: "RES, 0, 5%, 0.063 W, 0402"
R6: "RES, 47 k, 5%, 0.063 W, 0402"
R8: "RES, 21.5 k, 1%, 0.063 W, 0402"
R9: "RES, 10.0 k, 1%, 0.063 W, 0402"
R10 R15 R20: "RES, 1.00 M, 1%, 0.1 W, 0402"
R11: "RES, 11.8 k, 1%, 0.063 W, 0402"
R12: "RES, 8.06 k, 1%, 0.063 W, 0402"
R17: "RES, 200 k, 1%, 0.1 W, 0402"
R18: "RES, 4.99 k, 1%, 0.063 W, 0402"
R21 R22: "RES, 100 k, 1%, 0.1 W, 0402"
R23 R30: "RES, 51.1 k, 1%, 0.063 W, 0402"
R24 R25 R28 R29: "RES, 10.0 M, 1%, 0.063 W, 0402"
R26 R27: "RES, 40.2 k, 1%, 0.063 W, 0402"
R31 R32: "RES, 3.3 k, 5%, 0.063 W, 0402"
TP1 TP2 TP3 TP4 TP5: library part TP_SM_1MM, "1mm Test Point, SMT"
TP6: library part PogoPad, "Pad for Pogo Pin Connector"
U1: "Single Output High PSRR LDO, 200 mA, Fixed 3 V Output, 2.7 to 5.5 V Input, 5-pin SOT-23 (DBV), -40 to 85 degC, Green (RoHS & no Sb/Br)"
U2: "Single Micropower Precision Op Amp"
U3: "Precision Micropower Shunt Voltage Reference, 3-pin SOT-23"
U4: library part RF430CL331H, "The Texas Instruments Dynamic NFC Interface Transponder RF430CL331H is an NFC Tag Type 4 device  that combines a wireless NFC interface and a wired SPI or I2C interface to connect the device to a host."
U5: "LOW INPUT VOLTAGE STEP-UP CONVERTER IN 6 PIN SC-70 PACKAGE, DCK0006A"
U6: library part BMA250, "14 bit, digital, triaxial acceleration sensor with intelligent on-chip motion triggered interrupt controller"
U7: "High-Accuracy, Low-Power, Digital Temperature Sensor With SMBus(TM)/Two-Wire Serial Interface, DRL0006A"
U8: "Low-Power, 2-Channel, 24-Bit Analog Front-End for Biopotential Measurement, PBS0032A"
U9: "Mixed-Signal Microcontrollers, RGC0064B"
Y1: "Crystal, 32.768kHz, 12.5pF, SMD"
ZZ1: library part AssemblyNoteLabel
ZZ2 ZZ3 ZZ4: library part AssemblyNote

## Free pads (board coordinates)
  round 0 hole 3.762 unplated: 0(55.601,127) 0(87.909,88.062) 0(121.183,127.051)

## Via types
v1: diameter 0.864, hole 0.406, Top Layer to Bottom Layer, 113 vias
v2: diameter 0.5, hole 0.2, Top Layer to Bottom Layer, 13 vias

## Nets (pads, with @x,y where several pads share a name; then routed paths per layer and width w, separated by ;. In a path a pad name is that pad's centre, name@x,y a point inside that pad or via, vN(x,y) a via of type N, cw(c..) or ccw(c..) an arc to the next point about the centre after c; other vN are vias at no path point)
3V: C3.1 C4.1 C35.1 R4.2 R5.2 R15.2 U1.1 U1.3 U5.4 | length 53.6
  Top Layer w0.254: U1.3@93.148,102.55 U1.3@93.226,102.628 ; 94.386,100.178 94.488,100.178 ; C3.1@94.669,102.55 C3.1@94.747,102.628 ; 96.663,106.02 96.663,106.061
  Top Layer w0.54: R15.2@93.015,104.496 96.663,104.496 ; U1.1@93.148,100.65 93.914,100.65 94.386,100.178 ; U1.3@93.148,102.55 C3.1@94.669,102.55 ; 94.488,100.178 97.841,100.178 98.349,100.686 98.349,101.702 95.901,104.15 96.663,104.496 ; C3.1@94.747,102.628 C4.1@96.017,102.628 96.017,104.034 ; U5.4@95.646,109.662 95.646,110.632 96.012,110.998 97.485,110.998 97.993,110.49 ; C35.1@95.85,105.41 96.663,105.41 ; 96.663,106.02 96.663,105.41 ; 96.663,106.061 97.282,106.68 97.282,107.696 97.587,108.001 97.587,110.084 97.993,110.49 ; v1(100.635,113.132) 97.993,110.49 ; v1(103.175,115.672) 105.969,115.672 112.76,122.463 R5.2@112.76,124.816 ; R4.2@112.741,126.365 112.76,126.346 R5.2@112.76,124.861 ; 96.663,104.496 96.663,105.41
  Bottom Layer w0.54: v1(100.635,113.132) v1(103.175,115.672)
ADS1292_DRDY: 9.1 U8.22 U9.26 | length 11.3
  Top Layer w0.254: 9.1@89.383,132.258 90.221,132.258 90.246,132.283 ; U8.22@89.447,138.704 89.447,134.734 89.638,134.542 89.638,133.84 90.246,133.232 90.246,132.283 ; U9.26@89.471,128.962 89.471,130.974 90.246,131.75 90.246,132.283
ADS1292_ELA: C52.1 R30.1 TP4.1 | length 64.8
  Top Layer w0.54: v1(45.72,152.654) 45.72,153.416 47.092,154.788 92.253,154.788 93.523,153.518 C52.1@93.523,152.086 ; R30.1@83.765,151.409 83.765,154.733
  Bottom Layer w0.54: TP4.1@45.72,142.24 v1(45.72,152.654)
ADS1292_ERA: C48.1 R23.1 TP3.1 | length 63.2
  Top Layer w0.54: R23.1@85.039,151.437 v1(85.039,153.67) ; C48.1@94.793,152.086 96.063,153.356 v1(96.063,154.534)
  Bottom Layer w0.54: v1(85.039,153.67) 85.852,154.534 v1(96.063,154.534) 128.981,154.534 130.099,153.416 TP3.1@130.099,141.326
ADS1292_GPIO1: 6.1 U8.26 U9.9 | length 24
  Top Layer w0.254: U8.26@91.846,140.603 93.229,140.603 94.744,139.089 94.744,137.976 96.728,135.992 ; U9.9@94.621,124.812 95.5,124.812 96.024,125.336 97.067,125.336 v1@97.067,125.59 ; 6.1@95.301,131.674 96.171,131.674 v1(96.578,132.08) 96.734,132.236 96.734,135.992
  Bottom Layer w0.254: v1(96.578,132.08) 98.603,130.055 98.603,126.848 v1(97.079,125.324)
ADS1292_GPIO2: 7.1 U8.25 U9.25 | length 19.5
  Top Layer w0.254: U9.25@89.971,128.962 89.971,129.729 ; 89.97,129.73 89.97,130.864 90.87,131.764 91.313,131.764 ; 7.1@91.288,130.785 91.288,131.739 91.313,131.764 ; U8.25@91.846,140.103 92.987,140.103 94.29,138.8 94.29,137.866 96.317,135.839 96.317,133.401 95.58,132.664 92.71,132.664 91.81,131.764 91.313,131.764
ADS1292_IN1N: C46.1 R24.1 R25.2 U8.3 | length 12.8
  Top Layer w0.254: R24.1@89.297,152.202 89.967,152.202 ; U8.3@89.447,145.003 89.447,148.184 89.713,148.45 v1(89.713,148.946) ; 89.522,147.753 90.206,147.753 C46.1@90.891,148.438 ; v1(89.967,153.264) 89.967,152.202 ; R25.2@90.891,152.202 89.967,152.202
  Bottom Layer w0.254: v1(89.713,148.946) 89.713,150.932 89.967,151.186 v1(89.967,153.264)
ADS1292_IN1P: C54.1 R28.1 R29.2 U8.4 | length 9.1
  Top Layer w0.254: U8.4@88.947,145.003 88.947,149.246 89.408,149.708 C54.1@90.891,149.708 ; R28.1@89.297,150.932 90.094,150.932 ; 90.094,149.835 90.094,150.932 ; R29.2@90.891,150.932 90.094,150.932
ADS1292_IN2N: C44.1 R23.2 U8.5 | length 8.7
  Top Layer w0.254: C44.1@86.563,150.291 85.093,150.291 R23.2@85.039,150.237 85.039,149.447 85.395,149.092 86.279,149.092 86.563,148.807 88.447,146.924 U8.5@88.447,145.003
ADS1292_IN2P: C57.1 R30.2 U8.6 | length 9.5
  Top Layer w0.254: C57.1@82.241,150.263 83.711,150.263 R30.2@83.765,150.209 ; R30.2@83.711,150.209 83.711,149.359 84.433,148.638 86.091,148.638 87.947,146.782 U8.6@87.947,145.003
ADS1292_MAIN_CLKSEL: 14.1 U8.14 U9.32 | length 17.1
  Top Layer w0.254: U8.14@85.547,141.103 84.137,141.103 83.471,140.437 83.471,130.658 83.979,130.15 86.157,130.15 ; 14.1@86.157,130.912 86.157,130.15 ; U9.32@86.47,128.962 86.47,129.837 86.157,130.15
ADS1292_RESET: 8.1 U8.15 U9.31 | length 16.9
  Top Layer w0.254: 8.1@85.395,132.944 85.395,131.597 ; U8.15@85.547,140.603 85.527,140.583 84.433,140.583 83.925,140.075 83.925,132.128 84.455,131.597 85.395,131.597 ; U9.31@86.97,128.962 86.97,131.368 86.741,131.597 85.395,131.597
ADS1292_RESP_MODP/IN3N: R26.2 U8.32 | length 2.4
  Top Layer w0.254: U8.32@91.846,143.603 93.514,143.603 93.523,143.612 R26.2@93.523,144.328
ADS1292_RESP_MODP/IN3P: R27.2 TP1.1 U8.31 | length 11.9
  Top Layer w0.254: U8.31@91.846,143.103 93.568,143.103 R27.2@94.793,144.328 97.795,144.328 98.603,145.136 TP1.1@98.603,149.454
ADS1292_RLD: R22.2 TP5.1 | length 97.3
  Top Layer w0.254: R22.2@103.267,147.168 104.953,147.168 v1(105.461,146.66)
  Bottom Layer w0.254: TP5.1@88.443,64.618 96.571,64.618 101.93,69.977 101.93,105.283 102.438,105.791 102.438,112.141 106.731,116.434 106.731,118.974 105.994,119.71 105.994,146.126 v1(105.461,146.66)
ADS1292_SPI_CS: 10.1 U8.18 U9.13 | length 22.1
  Top Layer w0.254: 85.487,135.23 10.1@86.665,135.23 ; 87.401,137.328 86.614,136.541 85.995,136.541 85.395,135.941 85.395,134.722 85.649,134.468 87.274,134.468 88.138,133.603 v1(88.138,131.953) ; 87.447,137.374 U8.18@87.447,138.704 ; v1(89.484,127.356) 90.373,127.356 90.742,126.987 92.392,126.987 92.568,126.812 U9.13@94.621,126.812
  Bottom Layer w0.254: v1(88.138,131.953) 88.138,127.94 88.722,127.356 v1(89.484,127.356)
ADS1292_SPI_DIN: 12.1 U8.19 U9.15 | length 27
  Top Layer w0.254: 12.1@82.093,135.23 82.093,135.992 82.347,136.246 v1(82.347,136.5) ; v1(87.681,136.5) 87.947,136.766 U8.19@87.947,138.704 ; U9.15@94.621,127.812 95.909,127.812 v1(96.342,128.245)
  Bottom Layer w0.254: v1(82.347,136.5) v1(87.681,136.5) 87.3,136.119 87.3,133.706 88.394,132.612 88.411,132.612 88.797,132.226 88.797,129.135 89.687,128.245 v1(96.342,128.245)
ADS1292_SPI_DOUT: 11.1 U8.21 U9.16 | length 35
  Top Layer w0.254: v1(88.947,134.091) U8.21@88.947,138.704 88.947,140.052 v1(89.713,140.818) ; U9.16@94.621,128.312 95.241,128.312 95.377,128.448 v1(95.377,129.362) ; v1(100.127,147.93) 100.127,149.2 11.1@102.159,151.232
  Bottom Layer w0.254: v1(88.947,134.091) 88.947,133.532 89.535,132.944 91.575,132.944 95.157,129.362 v1(95.377,129.362) ; v1(89.713,140.818) 93.777,144.882 97.079,144.882 v1(100.127,147.93)
ADS1292_SPI_SCLK: 13.1 U8.20 U9.14 | length 34.6
  Top Layer w0.254: 13.1@82.042,147.32 82.804,146.558 84.328,146.558 v1(84.836,146.05) ; v1(87.935,140.31) 88.447,139.798 U8.20@88.447,138.704 88.447,135.208 v1(88.24,135.001) ; U9.14@94.621,127.312 95.497,127.312 v1(95.961,126.848)
  Bottom Layer w0.254: v1(84.836,146.05) 84.836,143.408 v1(87.935,140.31) ; v1(88.24,135.001) 88.24,133.706 89.205,132.74 89.205,129.515 90.043,128.676 95.623,128.676 96.08,129.134 96.596,129.134 97.155,128.575 97.155,127.508 96.495,126.848 v1(95.961,126.848)
ADS1292_START: 15.1 U8.16 U9.30 | length 15.2
  Top Layer w0.254: 84.379,137.77 15.1@85.141,137.77 ; U8.16@85.547,140.103 84.661,140.103 84.379,139.821 84.379,138.204 84.379,134.722 85.141,133.96 86.919,133.96 87.47,133.408 U9.30@87.47,128.962
ADS1292_VCAP1: C55.1 U8.11 | length 4.6
  Top Layer w0.254: C55.1@80.968,142.603 U8.11@85.547,142.603
ADS1292_VCAP2: C56.1 U8.27 | length 6.8
  Top Layer w0.254: U8.27@91.846,141.103 93.645,141.103 95.198,139.55 95.198,138.022 95.704,137.516 C56.1@96.225,137.516
ADS1292_VREFP: C50.1 C51.1 U8.9 | length 5.9
  Top Layer w0.254: C51.1@81.829,145.58 C51.1@81.534,145.58 81.642,145.472 C50.1@83.058,145.472 83.89,145.472 84.074,145.288 84.074,144.018 84.489,143.603 U8.9@85.547,143.603
ADS_AVCC: C22.1 C23.1 C24.1 C39.1 C40.1 L6.2 R8.2 R24.2 R28.2 U2.5 U8.12 | length 21.4
  Top Layer w0.254: U2.5@76.297,143.8 77.252,143.8 77.47,144.018 v1(77.47,144.78) ; v1(76.708,145.542) 76.757,145.493 77.929,145.493 78.537,146.101 R8.2@78.537,147.33 ; v1(78.486,136.906) 78.85,137.27 79.703,137.27 C23.1@79.761,137.212 ; v1(79.079,141.106) C39.1@81.031,141.106 ; L6.2@79.807,135.522 79.807,137.166 C23.1@79.761,137.212 ; v1(80.823,148.184) C24.1@80.823,150.378 ; C22.1@81.031,137.212 C23.1@79.761,137.212 ; C39.1@81.331,141.164 C40.1@82.601,141.164 83.54,142.103 U8.12@85.547,142.103 ; v1(88.097,149.362) R28.2@88.097,150.932 R24.2@88.097,152.202
ADS_AVSS: C22.2 C23.2 C24.2 C39.2 C40.2 C44.2 C50.2 C51.2 C55.2 C56.2 C57.2 R3.2 R9.1 R12.1 R25.1 R29.1 U2.2 U3.2 U8.10 U8.13 | length 43.8
  Top Layer w0.254: v1(68.631,119.99) R3.2@70.446,119.99 ; v1(72.811,142.85) U2.2@73.897,142.85 ; R12.1@75.951,148.117 74.981,149.088 74.981,151.74 75.677,152.436 78.929,152.436 80.757,152.436 ; v1@78.029,143.612 v1(78.283,143.612) 78.283,143.205 78.892,142.596 C55.2@79.761,142.596 ; v1(80.01,146.304) 80.01,144.272 80.302,143.98 C51.2@81.534,143.98 81.826,144.272 C50.2@83.058,144.272 83.058,143.51 83.464,143.104 84.074,143.104 U8.10@85.547,143.103 ; C24.2@80.823,151.578 v1(80.823,153.518) ; C22.2@81.031,138.412 79.761,138.412 79.761,139.906 81.031,139.906 82.197,139.906 C40.2@82.428,140.137 ; C57.2@82.241,151.863 v1(82.241,153.496) ; C40.2@82.601,139.964 82.601,140.068 83.894,141.362 ; 83.894,141.373 84.125,141.603 U8.13@85.547,141.603 ; C44.2@86.563,151.891 v1(86.563,153.416) ; R29.1@92.091,150.932 R25.1@92.091,152.202 v1(92.091,153.426) ; C56.2@97.425,137.516 97.425,136.916 v1(97.841,136.5)
  Top Layer w0.54: v1(104.191,135.484) R9.1@104.191,137.17
  other v1: 80.061,139.906
ADS_DVCC: C15.1 C19.1 C20.1 C21.1 C41.1 C42.1 L5.2 L6.1 U8.23 | length 23.8
  Top Layer w0.254: L6.1@79.807,133.922 80.061,133.668 v1(80.061,132.436) ; U8.23@89.947,138.704 89.947,134.734 89.992,134.689 89.992,134.341 90.211,134.122 C42.1@90.729,134.122 C41.1@91.999,134.122 C19.1@93.269,134.122 C20.1@94.539,134.122 ; C20.1@94.567,134.15 C20.1@94.539,134.122 ; v1(95.504,133.858) 95.504,133.896 95.278,134.122 C20.1@94.539,134.122 ; v1(97.841,132.944) C21.1@97.841,134.122 98.511,133.452 L5.2@99.835,133.452 99.835,134.176 100.889,135.23 100.889,139.294 100.127,140.056 C15.1@100.127,141.296
ANTENNA: D1.2 D2.2 R13.2 R14.2 | length 600.2
  Top Layer w0.4: v1(77.267,95.86) 78.029,96.622 98.857,96.622 98.857,73 76.505,73 76.505,97.13 99.365,97.13 99.365,72.492 75.997,72.492 75.997,97.638 99.873,97.638 99.873,71.984 75.438,71.984 75.438,98.044 76.251,98.857 76.251,103.631 76.806,104.055 77.897,104.055 ; v1(77.267,100.178) 77.267,101.702 77.876,102.311 84.633,102.311 84.963,102.641 D2.2@84.963,103.239 ; D1.2@77.897,106.379 77.897,104.055 ; R13.2@79.675,104.055 77.897,104.055 ; 81.199,102.311 R14.2@81.199,104.055
  Bottom Layer w0.4: 75.438,97.079 75.438,71.984 99.873,71.984 99.873,97.638 77.267,97.638 v1(77.267,100.178) ; 75.489,97.13 99.365,97.13 99.365,72.492 75.997,72.492 75.997,96.622 98.857,96.622 98.857,73 76.505,73 76.505,95.098 v1(77.267,95.86)
BMA_AVCC: C16.1 C37.1 L4.1 U6.7 | length 5.4
  Top Layer w0.254: C16.1@74.219,128.647 C37.1@75.489,128.647 ; U6.7@75.222,127.111 75.222,128.38 C37.1@75.489,128.647 ; L4.1@76.975,129.896 76.975,129.045 76.735,128.805 75.647,128.805 C37.1@75.489,128.647
BMA_DVCC: C17.1 C36.1 L3.2 L4.2 U6.1 U6.3 U6.11 | length 28.6
  Top Layer w0.254: U6.11@75.747,125.586 75.747,124.794 75.463,124.511 74.117,124.511 72.847,125.781 72.847,129.616 74.346,131.115 78.207,131.115 78.575,130.747 L4.2@78.575,129.896 78.575,129.096 79.553,128.118 L3.2@80.531,128.118 80.569,128.08 C17.1@80.569,126.224 C36.1@79.299,126.224 78.912,126.611 U6.3@76.772,126.611 ; U6.1@76.772,125.611 76.772,125.158 77.216,124.714 78.08,124.714 78.562,125.197 78.562,126.585
BMA_INT1: U6.5 U9.38 | length 11
  Top Layer w0.254: U6.5@76.247,127.136 76.247,127.657 76.382,127.792 v1(76.857,127.792) ; v1(82.347,126.848) 83.363,125.832 ; 83.383,125.812 U9.38@85.821,125.812
  Bottom Layer w0.254: v1(76.857,127.792) 77.826,127.792 78.844,126.774 79.39,126.774 79.464,126.848 v1(82.347,126.848)
BMA_INT2: U6.6 U9.33 | length 11.4
  Top Layer w0.254: U6.6@75.747,127.136 75.747,127.88 76.319,128.451 77.394,128.451 77.721,128.778 v1(77.8,128.778) ; v1(84.099,128.778) 84.566,128.312 U9.33@85.821,128.312
  Bottom Layer w0.254: v1(77.8,128.778) v1(84.099,128.778)
BOOST_INPUT: BT1.1 BT2.1 C34.1 L7.1 R16.1 U5.1 | length 94.5
  Top Layer w0.254: L7.1@89.739,107.681 L7.1@89.748,107.672 ; v1(94.285,113.132) v1@94.447,112.97
  Top Layer w0.5: 75.235,110.592 75.235,101.702 v1(75.489,101.448)
  Top Layer w0.54: BT2.1@65.964,127.991 65.964,119.863 75.235,110.592 ; v1(79.553,101.448) 85.141,101.448 87.274,103.581 87.274,109.906 88.113,110.744 92.456,110.744 93.828,112.116 C34.1@94.447,112.116 ; 87.274,107.696 L7.1@89.739,107.681 ; L7.1@89.959,107.35 R16.1@92.659,107.35 93.145,107.35 93.561,106.934 94.132,106.934 94.346,107.148 U5.1@94.346,107.762 ; C34.1@94.285,112.278 v1(94.285,113.132) ; v1(104.699,128.287) BT1.1@111.048,128.287
  Bottom Layer w0.54: v1(75.489,101.448) v1(79.553,101.448) ; v1(94.285,113.132) 94.285,115.926 98.349,119.99 100.381,119.99 101.997,121.606 101.997,127.448 102.836,128.287 v1(104.699,128.287)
